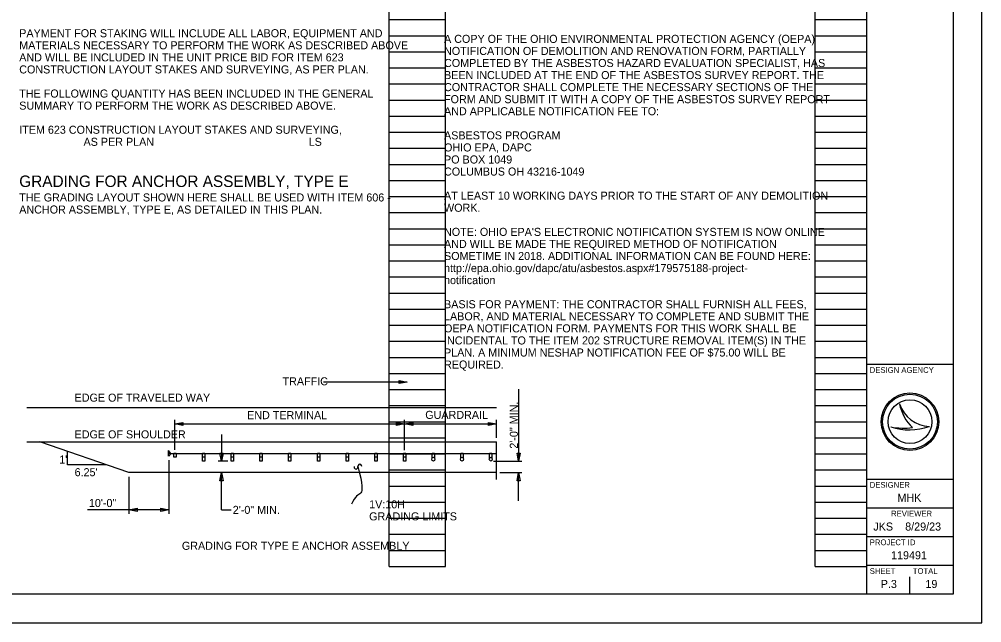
# Model space of a CAD drawing. Extents: x 0 to 34, y 0 to 22.
# Drawn here: x 17.24 to 34, y 0 to 10.51 of the extents above; entities that cross this region are included whole.
import ezdxf

# ---------------------------------------------------------------- set-up
doc = ezdxf.new("R2010")
doc.units = 0
for name, color, linetype in [('SH_Border', 7, 'Continuous'), ('SH_Cut_Line', 7, 'Continuous'), ('SH_Data', 7, 'Continuous'), ('TX_P_Misc', 7, 'Continuous'), ('XS_P_Text_Info', 7, 'Continuous')]:
    doc.layers.add(name, color=color, linetype=linetype)

msp = doc.modelspace()

# ---------------------------------------------------------------- linework, layer by layer
at = {"layer": 'SH_Border'}
for p, q in [((32, 0.5), (32, 21.5)), ((32, 4.5), (33.5, 4.5)), ((32, 2.5), (33.5, 2.5)), ((32, 2), (33.5, 2)), ((32, 1.5), (33.5, 1.5)), ((32, 1), (33.5, 1))]:
    msp.add_line(p, q, dxfattribs=at)
msp.add_lwpolyline([(1.5, 21.5), (33.5, 21.5), (33.5, 0.5), (1.5, 0.5)], close=True, dxfattribs=at)
at = {"layer": 'SH_Cut_Line'}
msp.add_lwpolyline([(0, 0), (34, 0), (34, 22), (0, 22)], close=True, dxfattribs=at)
at = {"layer": 'SH_Data'}
for p, q in [((23.68, 0.98), (23.68, 21.14)), ((24.66, 0.98), (24.66, 21.14)), ((31.1, 0.98), (31.1, 21.14)), ((32, 0.98), (32, 21.14)), ((23.68, 10.5), (24.66, 10.5)), ((31.1, 10.5), (32, 10.5)), ((23.68, 10.22), (24.66, 10.22)), ((31.1, 10.22), (32, 10.22)), ((23.68, 9.94), (24.66, 9.94)), ((31.1, 9.94), (32, 9.94)), ((23.68, 9.66), (24.66, 9.66)), ((31.1, 9.66), (32, 9.66)), ((23.68, 9.38), (24.66, 9.38)), ((31.1, 9.38), (32, 9.38)), ((23.68, 9.1), (24.66, 9.1)), ((31.1, 9.1), (32, 9.1)), ((23.68, 8.82), (24.66, 8.82)), ((31.1, 8.82), (32, 8.82)), ((23.68, 8.54), (24.66, 8.54)), ((31.1, 8.54), (32, 8.54)), ((23.68, 8.26), (24.66, 8.26)), ((31.1, 8.26), (32, 8.26)), ((23.68, 7.98), (24.66, 7.98)), ((31.1, 7.98), (32, 7.98)), ((23.68, 7.7), (24.66, 7.7)), ((31.1, 7.7), (32, 7.7)), ((23.68, 7.42), (24.66, 7.42)), ((31.1, 7.42), (32, 7.42)), ((23.68, 7.14), (24.66, 7.14)), ((31.1, 7.14), (32, 7.14)), ((23.68, 6.86), (24.66, 6.86)), ((31.1, 6.86), (32, 6.86)), ((23.68, 6.58), (24.66, 6.58)), ((31.1, 6.58), (32, 6.58)), ((23.68, 6.3), (24.66, 6.3)), ((31.1, 6.3), (32, 6.3)), ((23.68, 6.02), (24.66, 6.02)), ((31.1, 6.02), (32, 6.02)), ((23.68, 5.74), (24.66, 5.74)), ((31.1, 5.74), (32, 5.74)), ((23.68, 5.46), (24.66, 5.46)), ((31.1, 5.46), (32, 5.46)), ((23.68, 5.18), (24.66, 5.18)), ((31.1, 5.18), (32, 5.18)), ((23.68, 4.9), (24.66, 4.9)), ((31.1, 4.9), (32, 4.9)), ((23.68, 4.62), (24.66, 4.62)), ((31.1, 4.62), (32, 4.62)), ((23.68, 4.34), (24.66, 4.34)), ((31.1, 4.34), (32, 4.34)), ((23.68, 4.06), (24.66, 4.06)), ((31.1, 4.06), (32, 4.06)), ((23.68, 3.78), (24.66, 3.78)), ((31.1, 3.78), (32, 3.78)), ((32.567, 3.81), (32.567, 3.81)), ((23.68, 3.5), (24.66, 3.5)), ((31.1, 3.5), (32, 3.5)), ((32.417, 3.41), (32.417, 3.41)), ((32.75, 3.5), (32.75, 3.5)), ((33.087, 3.419), (33.087, 3.419)), ((23.68, 3.22), (24.66, 3.22)), ((31.1, 3.22), (32, 3.22)), ((23.68, 2.94), (24.66, 2.94)), ((31.1, 2.94), (32, 2.94)), ((23.68, 2.66), (24.66, 2.66)), ((31.1, 2.66), (32, 2.66)), ((23.68, 2.38), (24.66, 2.38)), ((31.1, 2.38), (32, 2.38)), ((23.68, 2.1), (24.66, 2.1)), ((31.1, 2.1), (32, 2.1)), ((23.68, 1.82), (24.66, 1.82)), ((31.1, 1.82), (32, 1.82)), ((23.68, 1.54), (24.66, 1.54)), ((31.1, 1.54), (32, 1.54)), ((23.68, 1.26), (24.66, 1.26)), ((31.1, 1.26), (32, 1.26)), ((23.68, 0.98), (24.66, 0.98)), ((31.1, 0.98), (32, 0.98)), ((32.375, 0.675), (32.375, 0.675)), ((32.75, 0.5), (32.75, 0.8))]:
    msp.add_line(p, q, dxfattribs=at)
for radius in [0.5, 0.477, 0.477, 0.382]:
    msp.add_circle((32.75, 3.5), radius, dxfattribs=at)
for centre, radius, start, end in [((33.116, 3.998), 0.58, 198.9257, 198.9319), ((33.347, 3.97), 0.796, 191.6379, 191.6421), ((33.116, 3.998), 0.58, 198.9319, 267.1657), ((33.347, 3.97), 0.796, 191.6421, 226.0947), ((32.739, 4.37), 1.013, 251.4576, 290.0832), ((32.648, 4.654), 1.266, 259.4964, 259.4995), ((32.739, 4.37), 1.013, 251.4527, 251.4576), ((32.648, 4.654), 1.266, 259.4995, 276.6672)]:
    msp.add_arc(centre, radius, start, end, dxfattribs=at)
at = {"layer": 'TX_P_Misc'}
for p, q in [((23.994, 4.191), (22.537, 4.191)), ((25.936, 4.065), (25.936, 2.813)), ((17.375, 3.747), (25.551, 3.747)), ((19.951, 3.01), (19.951, 3.531)), ((23.951, 3.005), (23.951, 3.531)), ((25.551, 3.217), (25.551, 3.531)), ((19.951, 3.461), (23.951, 3.461)), ((23.951, 3.461), (25.551, 3.461)), ((20.762, 3.277), (20.762, 2.813)), ((17.375, 3.147), (25.551, 3.147)), ((19.151, 2.613), (17.6, 3.147)), ((25.551, 2.494), (25.551, 3.147)), ((18.082, 2.749), (18.082, 2.982)), ((19.88, 2.947), (19.84, 2.997)), ((19.84, 2.898), (19.84, 2.997)), ((19.88, 2.947), (19.84, 2.947)), ((19.88, 2.947), (19.84, 2.898)), ((19.88, 2.947), (25.551, 2.947)), ((19.931, 2.881), (19.931, 2.947)), ((19.972, 2.947), (19.931, 2.947)), ((19.972, 2.881), (19.931, 2.881)), ((19.972, 2.947), (19.972, 2.881)), ((20.431, 2.814), (20.431, 2.947)), ((20.472, 2.947), (20.431, 2.947)), ((20.472, 2.881), (20.431, 2.881)), ((20.472, 2.947), (20.472, 2.814)), ((20.931, 2.813), (20.931, 2.947)), ((20.972, 2.947), (20.931, 2.947)), ((20.972, 2.88), (20.931, 2.88)), ((20.972, 2.947), (20.972, 2.813)), ((21.431, 2.813), (21.431, 2.947)), ((21.472, 2.947), (21.431, 2.947)), ((21.472, 2.88), (21.431, 2.88)), ((21.472, 2.947), (21.472, 2.813)), ((21.931, 2.813), (21.931, 2.947)), ((21.972, 2.947), (21.931, 2.947)), ((21.972, 2.88), (21.931, 2.88)), ((21.972, 2.947), (21.972, 2.813)), ((22.431, 2.813), (22.431, 2.947)), ((22.472, 2.947), (22.431, 2.947)), ((22.472, 2.88), (22.431, 2.88)), ((22.472, 2.947), (22.472, 2.813)), ((22.931, 2.813), (22.931, 2.947)), ((22.972, 2.947), (22.931, 2.947)), ((22.972, 2.88), (22.931, 2.88)), ((22.972, 2.947), (22.972, 2.813)), ((23.431, 2.813), (23.431, 2.947)), ((23.472, 2.947), (23.431, 2.947)), ((23.472, 2.88), (23.431, 2.88)), ((23.472, 2.947), (23.472, 2.813)), ((23.931, 2.813), (23.931, 2.947)), ((23.972, 2.947), (23.931, 2.947)), ((23.972, 2.88), (23.931, 2.88)), ((23.972, 2.947), (23.972, 2.813)), ((24.431, 2.868), (24.431, 2.947)), ((24.472, 2.947), (24.431, 2.947)), ((24.472, 2.947), (24.472, 2.868)), ((24.931, 2.868), (24.931, 2.947)), ((24.972, 2.947), (24.931, 2.947)), ((24.972, 2.947), (24.972, 2.868)), ((25.431, 2.868), (25.431, 2.947)), ((25.472, 2.947), (25.431, 2.947)), ((25.472, 2.947), (25.472, 2.868)), ((18.756, 2.749), (18.082, 2.749)), ((19.844, 2.832), (19.844, 1.894)), ((20.472, 2.814), (20.431, 2.814)), ((20.875, 2.813), (20.706, 2.813)), ((20.972, 2.813), (20.931, 2.813)), ((21.472, 2.813), (21.431, 2.813)), ((21.972, 2.813), (21.931, 2.813)), ((22.472, 2.813), (22.431, 2.813)), ((22.972, 2.813), (22.931, 2.813)), ((23.472, 2.813), (23.431, 2.813)), ((23.972, 2.813), (23.931, 2.813)), ((25.498, 2.813), (25.992, 2.813)), ((25.551, 2.613), (19.151, 2.613)), ((19.151, 2.543), (19.151, 1.894)), ((20.762, 1.964), (20.762, 2.613)), ((25.607, 2.613), (25.992, 2.613)), ((25.936, 2.123), (25.936, 2.613)), ((19.844, 1.964), (18.428, 1.964)), ((20.762, 1.964), (20.928, 1.964))]:
    msp.add_line(p, q, dxfattribs=at)
for points in [[(23.854, 4.219), (23.994, 4.191), (23.854, 4.163)], [(20.091, 3.433), (19.951, 3.461), (20.091, 3.489)], [(23.811, 3.489), (23.951, 3.461), (23.811, 3.433)], [(24.091, 3.433), (23.951, 3.461), (24.091, 3.489)], [(25.411, 3.489), (25.551, 3.461), (25.411, 3.433)], [(20.79, 2.953), (20.762, 2.813), (20.734, 2.953)], [(25.964, 2.953), (25.936, 2.813), (25.908, 2.953)], [(20.734, 2.473), (20.762, 2.613), (20.79, 2.473)], [(25.908, 2.473), (25.936, 2.613), (25.964, 2.473)], [(19.291, 1.936), (19.151, 1.964), (19.291, 1.992)], [(19.704, 1.992), (19.844, 1.964), (19.704, 1.936)]]:
    msp.add_lwpolyline(points, close=True, dxfattribs=at)
for centre in [(24.451, 2.847), (24.951, 2.847), (25.451, 2.847)]:
    msp.add_ellipse(centre, major_axis=(0, 0.0334), ratio=0.8, dxfattribs=at)
for centre, start_param, end_param in [((23.104, 2.719), 4.712389, 7.853982), ((23.172, 2.719), 1.570796, 4.712389)]:
    msp.add_ellipse(centre, major_axis=(0, -0.0425), ratio=0.8, start_param=start_param, end_param=end_param, dxfattribs=at)
msp.add_open_spline([(23.138, 2.719), (23.304, 2.062), (23.138, 2.374), (23.028, 2.062)], degree=3, dxfattribs=at)
at = {"layer": 'XS_P_Text_Info'}
msp.add_line((20.875, 2.613), (20.706, 2.613), dxfattribs=at)

# ---------------------------------------------------------------- texts
at = {"layer": 'SH_Data'}
for s, height, p in [('DESIGN AGENCY', 0.1, (32.05, 4.35)), ('DESIGNER', 0.1, (32.05, 2.35)), ('MHK', 0.14, (32.532, 2.105)), ('REVIEWER', 0.1, (32.422, 1.85)), ('JKS', 0.14, (32.112, 1.605)), ('8/29/23', 0.14, (32.667, 1.605)), ('PROJECT ID', 0.1, (32.05, 1.35)), ('119491', 0.14, (32.421, 1.105)), ('SHEET', 0.1, (32.05, 0.85)), ('TOTAL', 0.1, (32.8, 0.85)), ('P.3', 0.14, (32.241, 0.605)), ('19', 0.14, (33.019, 0.605))]:
    msp.add_text(s, height=height, dxfattribs=at).set_placement(p)
at = {"layer": 'TX_P_Misc'}
for s, height, p in [('PAYMENT FOR STAKING WILL INCLUDE ALL LABOR, EQUIPMENT AND ', 0.14, (17.24, 10.193)), ('A COPY OF THE OHIO ENVIRONMENTAL PROTECTION AGENCY (OEPA) ', 0.14, (24.637, 10.095)), ('MATERIALS NECESSARY TO PERFORM THE WORK AS DESCRIBED ABOVE ', 0.14, (17.24, 9.983)), ('AND WILL BE INCLUDED IN THE UNIT PRICE BID FOR ITEM 623 ', 0.14, (17.24, 9.773)), ('NOTIFICATION OF DEMOLITION AND RENOVATION FORM, PARTIALLY ', 0.14, (24.637, 9.885)), ('COMPLETED BY THE ASBESTOS HAZARD EVALUATION SPECIALIST, HAS ', 0.14, (24.637, 9.675)), ('CONSTRUCTION LAYOUT STAKES AND SURVEYING, AS PER PLAN.', 0.14, (17.24, 9.563)), ('BEEN INCLUDED AT THE END OF THE ASBESTOS SURVEY REPORT. THE ', 0.14, (24.637, 9.465)), ('CONTRACTOR SHALL COMPLETE THE NECESSARY SECTIONS OF THE ', 0.14, (24.637, 9.255)), ('THE FOLLOWING QUANTITY HAS BEEN INCLUDED IN THE GENERAL ', 0.14, (17.24, 9.143)), ('SUMMARY TO PERFORM THE WORK AS DESCRIBED ABOVE.', 0.14, (17.24, 8.933)), ('FORM AND SUBMIT IT WITH A COPY OF THE ASBESTOS SURVEY REPORT ', 0.14, (24.637, 9.045)), ('AND APPLICABLE NOTIFICATION FEE TO:   ', 0.14, (24.637, 8.835)), ('ITEM 623 CONSTRUCTION LAYOUT STAKES AND SURVEYING, ', 0.14, (17.24, 8.513)), ('ASBESTOS PROGRAM ', 0.14, (24.637, 8.415)), ('AS PER PLAN     ', 0.14, (18.36, 8.303)), ('LS', 0.14, (22.28, 8.303)), ('OHIO EPA, DAPC', 0.14, (24.637, 8.205)), ('PO BOX 1049', 0.14, (24.637, 7.995)), ('COLUMBUS OH 43216-1049', 0.14, (24.637, 7.785)), ('GRADING FOR ANCHOR ASSEMBLY, TYPE E', 0.2, (17.24, 7.586)), ('THE GRADING LAYOUT SHOWN HERE SHALL BE USED WITH ITEM 606 - ', 0.14, (17.24, 7.334)), ('AT LEAST 10 WORKING DAYS PRIOR TO THE START OF ANY DEMOLITION ', 0.14, (24.637, 7.365)), ('ANCHOR ASSEMBLY, TYPE E, AS DETAILED IN THIS PLAN.', 0.14, (17.24, 7.124)), ('WORK.  ', 0.14, (24.637, 7.155)), ("NOTE: OHIO EPA'S ELECTRONIC NOTIFICATION SYSTEM IS NOW ONLINE ", 0.14, (24.637, 6.735)), ('AND WILL BE MADE THE REQUIRED METHOD OF NOTIFICATION ', 0.14, (24.637, 6.525)), ('SOMETIME IN 2018. ADDITIONAL INFORMATION CAN BE FOUND HERE: ', 0.14, (24.637, 6.315)), ('http://epa.ohio.gov/dapc/atu/asbestos.aspx#179575188-project-', 0.14, (24.637, 6.105)), ('notification  ', 0.14, (24.637, 5.895)), ('BASIS FOR PAYMENT: THE CONTRACTOR SHALL FURNISH ALL FEES, ', 0.14, (24.637, 5.475)), ('LABOR, AND MATERIAL NECESSARY TO COMPLETE AND SUBMIT THE ', 0.14, (24.637, 5.265)), ('OEPA NOTIFICATION FORM. PAYMENTS FOR THIS WORK SHALL BE ', 0.14, (24.637, 5.055)), ('INCIDENTAL TO THE ITEM 202 STRUCTURE REMOVAL ITEM(S) IN THE ', 0.14, (24.637, 4.845)), ('PLAN. A MINIMUM NESHAP NOTIFICATION FEE OF $75.00 WILL BE ', 0.14, (24.637, 4.635)), ('REQUIRED.', 0.14, (24.637, 4.425)), ('TRAFFIC', 0.14, (21.825, 4.133)), ('EDGE OF TRAVELED WAY', 0.14, (18.204, 3.849)), ('GUARDRAIL', 0.14, (24.31, 3.549)), ('END TERMINAL', 0.14, (21.208, 3.544)), ('EDGE OF SHOULDER', 0.14, (18.204, 3.21)), ("1'", 0.14, (17.936, 2.772)), ("6.25'", 0.14, (18.204, 2.551)), ('10\'-0"', 0.14, (18.453, 2.015)), ('2\'-0" MIN.', 0.14, (20.958, 1.895)), ('1V:10H', 0.14, (23.333, 1.992)), ('GRADING LIMITS', 0.14, (23.333, 1.782)), ('GRADING FOR TYPE E ANCHOR ASSEMBLY', 0.14, (20.072, 1.27))]:
    msp.add_text(s, height=height, dxfattribs=at).set_placement(p)
msp.add_text('2\'-0" MIN.', height=0.14, rotation=90, dxfattribs=at).set_placement((25.922, 3.03))

doc.saveas('drawing.dxf')
